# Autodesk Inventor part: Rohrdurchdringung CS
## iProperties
Created: 2009-05
Part Number: Rohrdurchdringung CS
Material: 1.0037 St 37-2
Document SubType Name: Blech
Designer: M. Fiedler
Density: 7.85 g/cm^3
Category: 200 Bauteil
Author: M. Fiedler
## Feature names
1. Trennen1
2. Grobblech1
3. Ausklinkung1
4. Ausklinkung2
